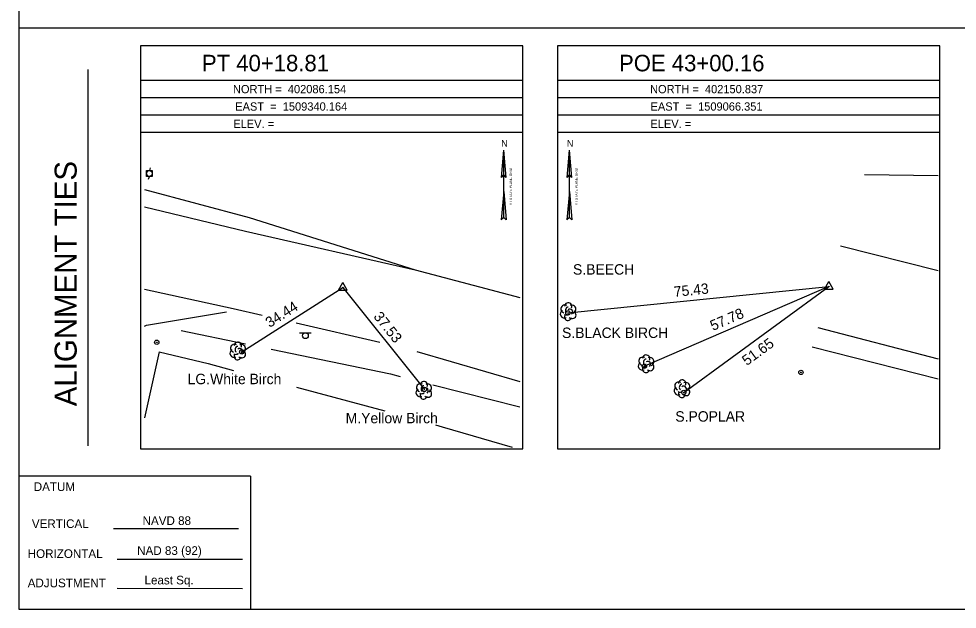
# Model space of a CAD drawing. Extents: x 1508412 to 1509054, y 401108 to 401963.
# Drawn here: x 1508411.9 to 1508681.9, y 401107.7 to 401277.6 of the extents above; entities that cross this region are included whole.
import ezdxf

# ---------------------------------------------------------------- set-up
doc = ezdxf.new("R2010")
doc.units = 0
for name, color, linetype in [('CBP', 7, 'Continuous'), ('CPH', 7, 'Continuous'), ('Default', 7, 'Continuous'), ('L_C', 7, 'Continuous'), ('LAWA', 7, 'Continuous'), ('LFP', 7, 'Continuous'), ('LTD', 7, 'Continuous'), ('LWS', 7, 'Continuous'), ('MPIP', 7, 'Continuous'), ('NBL1', 7, 'Continuous'), ('NBL2', 7, 'Continuous'), ('NNA_P', 7, 'Continuous'), ('PET', 7, 'Continuous'), ('PSU', 7, 'Continuous'), ('RDP', 7, 'Continuous'), ('SSGN', 7, 'Continuous'), ('UP', 7, 'Continuous')]:
    doc.layers.add(name, color=color, linetype=linetype)

msp = doc.modelspace()

# ---------------------------------------------------------------- linework, layer by layer
at = {"layer": 'CBP'}
for centre, radius in [((1508569.92, 401192.97), 0.625), ((1508569.92, 401192.97), 0.0833), ((1508476.08, 401181.78), 0.625), ((1508476.08, 401181.78), 0.0833), ((1508591.91, 401177.64), 0.625), ((1508591.91, 401177.64), 0.0833), ((1508528.62, 401170.99), 0.625), ((1508528.62, 401170.99), 0.0833), ((1508603.23, 401170.12), 0.625), ((1508603.23, 401170.12), 0.0833)]:
    msp.add_circle(centre, radius, dxfattribs=at)
at = {"layer": 'CPH'}
for p, q in [((1508503.89, 401199.55), (1508505.14, 401201.72)), ((1508506.39, 401199.55), (1508505.14, 401201.72)), ((1508643.72, 401199.83), (1508644.97, 401202)), ((1508646.22, 401199.83), (1508644.97, 401202)), ((1508644.97, 401200.55), (1508644.97, 401200.55)), ((1508503.89, 401199.55), (1508506.39, 401199.55)), ((1508505.14, 401200.27), (1508505.14, 401200.27)), ((1508643.72, 401199.83), (1508646.22, 401199.83))]:
    msp.add_line(p, q, dxfattribs=at)
for centre in [(1508644.97, 401200.55), (1508505.14, 401200.27)]:
    msp.add_circle(centre, 0.0833, dxfattribs=at)
at = {"layer": 'Default'}
for p, q in [((1508569.92, 401192.97), (1508644.97, 401200.55)), ((1508644.97, 401200.55), (1508591.91, 401177.64)), ((1508603.23, 401170.12), (1508644.97, 401200.55)), ((1508476.08, 401181.78), (1508505.14, 401200.27)), ((1508505.14, 401200.27), (1508528.62, 401170.99))]:
    msp.add_line(p, q, dxfattribs=at)
at = {"layer": 'LAWA'}
for points in [[(1508655.19, 401232.86), (1508676.45, 401232.52)], [(1508458.66, 401187.96), (1508477.14, 401184.1)], [(1508484.53, 401182.56), (1508518.81, 401175.41), (1508521.6, 401174.71)], [(1508531.02, 401172.33), (1508556.1, 401166)]]:
    msp.add_lwpolyline(points, dxfattribs=at)
at = {"layer": 'LFP'}
for radius in [0.625, 0.0833]:
    msp.add_circle((1508636.94, 401175.87), radius, dxfattribs=at)
at = {"layer": 'LTD'}
for p, q in [((1508569.95, 401193.41), (1508569.95, 401193.41)), ((1508569.95, 401193.41), (1508569.95, 401193.41)), ((1508474.9, 401182.09), (1508474.9, 401182.09)), ((1508474.9, 401182.09), (1508474.9, 401182.09)), ((1508592.38, 401178.4), (1508592.38, 401178.4)), ((1508592.38, 401178.4), (1508592.38, 401178.4)), ((1508602.7, 401171.23), (1508602.7, 401171.23)), ((1508602.7, 401171.23), (1508602.7, 401171.23)), ((1508528.42, 401170.77), (1508528.42, 401170.77)), ((1508528.42, 401170.77), (1508528.42, 401170.77))]:
    msp.add_line(p, q, dxfattribs=at)
for centre in [(1508569.99, 401194.85), (1508474.94, 401183.53), (1508592.43, 401179.84), (1508602.75, 401172.66), (1508528.46, 401172.2)]:
    msp.add_arc(centre, 1.05, 335.5272, 180.9563, dxfattribs=at)
for centre, major_axis, ratio, start_param, end_param in [((1508569.16, 401194.08), (1.21, -0.51), 0.895232, 1.570796, 4.712389), ((1508570.99, 401194), (-1.14, -0.48), 0.949671, 1.570796, 4.712389), ((1508568.86, 401192.7), (0.58, -1.04), 0.959034, 3.141593, 6.283185), ((1508569.49, 401192.66), (-0.625, -0.083), 0.423636, 0, 3.141593), ((1508569.74, 401193.87), (-0.208, -0.792), 0.645439, 3.141593, 6.283185), ((1508570.45, 401193.25), (-0.5, 0.667), 0.989748, 3.141593, 6.283185), ((1508570.95, 401192.58), (-1.09, 0.79), 0.841452, 1.570796, 4.712389), ((1508569.95, 401191.91), (0.26, 1.06), 0.942809, 1.570796, 4.712389), ((1508473.81, 401181.38), (0.58, -1.04), 0.959034, 3.141593, 6.283185), ((1508474.11, 401182.76), (1.21, -0.51), 0.895232, 1.570796, 4.712389), ((1508474.69, 401182.55), (-0.208, -0.792), 0.645439, 3.141593, 6.283185), ((1508475.4, 401181.93), (-0.5, 0.667), 0.989748, 3.141593, 6.283185), ((1508475.9, 401181.26), (-1.09, 0.79), 0.841452, 1.570796, 4.712389), ((1508475.94, 401182.68), (-1.14, -0.48), 0.949671, 1.570796, 4.712389), ((1508474.9, 401180.59), (0.26, 1.06), 0.942809, 1.570796, 4.712389), ((1508474.44, 401181.34), (-0.625, -0.083), 0.423636, 0, 3.141593), ((1508591.59, 401179.07), (1.21, -0.51), 0.895232, 1.570796, 4.712389), ((1508592.17, 401178.86), (-0.208, -0.792), 0.645439, 3.141593, 6.283185), ((1508592.88, 401178.23), (-0.5, 0.667), 0.989748, 3.141593, 6.283185), ((1508593.42, 401178.98), (-1.14, -0.48), 0.949671, 1.570796, 4.712389), ((1508591.3, 401177.69), (0.58, -1.04), 0.959034, 3.141593, 6.283185), ((1508592.38, 401176.9), (0.26, 1.06), 0.942809, 1.570796, 4.712389), ((1508591.92, 401177.65), (-0.625, -0.083), 0.423636, 0, 3.141593), ((1508593.38, 401177.57), (-1.09, 0.79), 0.841452, 1.570796, 4.712389), ((1508527.33, 401170.06), (0.58, -1.04), 0.959034, 3.141593, 6.283185), ((1508527.62, 401171.43), (1.21, -0.51), 0.895232, 1.570796, 4.712389), ((1508528.21, 401171.23), (-0.208, -0.792), 0.645439, 3.141593, 6.283185), ((1508528.92, 401170.6), (-0.5, 0.667), 0.989748, 3.141593, 6.283185), ((1508529.42, 401169.93), (-1.09, 0.79), 0.841452, 1.570796, 4.712389), ((1508529.46, 401171.35), (-1.14, -0.48), 0.949671, 1.570796, 4.712389), ((1508601.62, 401170.52), (0.58, -1.04), 0.959034, 3.141593, 6.283185), ((1508601.91, 401171.9), (1.21, -0.51), 0.895232, 1.570796, 4.712389), ((1508602.5, 401171.69), (-0.208, -0.792), 0.645439, 3.141593, 6.283185), ((1508603.2, 401171.06), (-0.5, 0.667), 0.989748, 3.141593, 6.283185), ((1508603.7, 401170.4), (-1.09, 0.79), 0.841452, 1.570796, 4.712389), ((1508603.75, 401171.81), (-1.14, -0.48), 0.949671, 1.570796, 4.712389), ((1508528.42, 401169.27), (0.26, 1.06), 0.942809, 1.570796, 4.712389), ((1508527.96, 401170.02), (-0.625, -0.083), 0.423636, 0, 3.141593), ((1508602.7, 401169.73), (0.26, 1.06), 0.942809, 1.570796, 4.712389), ((1508602.25, 401170.48), (-0.625, -0.083), 0.423636, 0, 3.141593)]:
    msp.add_ellipse(centre, major_axis=major_axis, ratio=ratio, start_param=start_param, end_param=end_param, dxfattribs=at)
at = {"layer": 'LWS'}
for points in [[(1508452.28, 401181.82), (1508448.04, 401162.82)], [(1508452.28, 401181.82), (1508466.44, 401178.39)], [(1508640.16, 401183.27), (1508676.45, 401174.06)], [(1508466.44, 401178.39), (1508473.7, 401176.45)], [(1508491.85, 401171.59), (1508517.26, 401164.79)], [(1508533.86, 401160.09), (1508531.92, 401160.64)], [(1508553.92, 401154.24), (1508533.86, 401160.09)]]:
    msp.add_lwpolyline(points, dxfattribs=at)
at = {"layer": 'MPIP'}
for radius in [0.625, 0.0833]:
    msp.add_circle((1508451.62, 401184.53), radius, dxfattribs=at)
at = {"layer": 'NBL1'}
msp.add_lwpolyline([(1508411.91, 401107.72), (1509051.91, 401107.72), (1509051.91, 401527.72), (1508411.91, 401527.72)], close=True, dxfattribs=at)
at = {"layer": 'NBL2'}
for p, q in [((1508411.91, 401275.05), (1509051.91, 401275.05)), ((1508431.91, 401154.72), (1508431.91, 401263.05)), ((1508556.91, 401259.88), (1508446.91, 401259.88)), ((1508676.91, 401259.88), (1508566.91, 401259.88)), ((1508556.91, 401254.88), (1508446.91, 401254.88)), ((1508676.91, 401254.88), (1508566.91, 401254.88)), ((1508556.91, 401249.88), (1508446.91, 401249.88)), ((1508676.91, 401249.88), (1508566.91, 401249.88)), ((1508556.91, 401244.88), (1508446.91, 401244.88)), ((1508676.91, 401244.88), (1508566.91, 401244.88)), ((1508478.57, 401145.97), (1508411.91, 401145.97)), ((1508478.57, 401145.97), (1508478.57, 401107.72)), ((1508478.57, 401145.97), (1508478.57, 401107.72)), ((1508439.15, 401130.95), (1508475.15, 401130.91)), ((1508440.26, 401122.17), (1508476.26, 401122.17)), ((1508440.26, 401113.74), (1508476.26, 401113.7))]:
    msp.add_line(p, q, dxfattribs=at)
for points in [[(1508446.91, 401153.88), (1508556.91, 401153.88), (1508556.91, 401269.88), (1508446.91, 401269.88)], [(1508566.91, 401153.88), (1508676.91, 401153.88), (1508676.91, 401269.88), (1508566.91, 401269.88)]]:
    msp.add_lwpolyline(points, close=True, dxfattribs=at)
at = {"layer": 'NNA_P'}
for p, q in [((1508550.75, 401231.99), (1508551.45, 401239.78)), ((1508551.45, 401220.4), (1508551.45, 401239.78)), ((1508552.14, 401231.99), (1508551.45, 401239.78)), ((1508569.65, 401231.99), (1508570.34, 401239.78)), ((1508570.35, 401220.4), (1508570.34, 401239.78)), ((1508571.04, 401231.99), (1508570.34, 401239.78)), ((1508550.75, 401231.99), (1508551.45, 401232.75)), ((1508552.14, 401231.99), (1508551.45, 401232.75)), ((1508569.65, 401231.99), (1508570.35, 401232.75)), ((1508571.04, 401231.99), (1508570.35, 401232.75)), ((1508551.45, 401227.93), (1508550.73, 401219.77)), ((1508551.45, 401227.93), (1508552.17, 401219.77)), ((1508570.35, 401227.93), (1508569.63, 401219.77)), ((1508570.35, 401227.93), (1508571.07, 401219.77)), ((1508551.45, 401220.4), (1508550.73, 401219.77)), ((1508551.45, 401220.4), (1508552.17, 401219.77)), ((1508570.35, 401220.4), (1508569.63, 401219.77)), ((1508570.35, 401220.4), (1508571.07, 401219.77))]:
    msp.add_line(p, q, dxfattribs=at)
at = {"layer": 'PET'}
for points in [[(1508448.04, 401223.49), (1508477.12, 401216.53), (1508525.99, 401205.41), (1508556.1, 401197.39)], [(1508648.35, 401212.32), (1508676.45, 401205.17)], [(1508448.04, 401199.84), (1508473.63, 401194.26), (1508481.9, 401192.37)], [(1508491.72, 401190.11), (1508515.78, 401184.6)], [(1508641.78, 401188.81), (1508676.45, 401179.78)], [(1508526.39, 401181.84), (1508556.1, 401173.27)]]:
    msp.add_lwpolyline(points, dxfattribs=at)
at = {"layer": 'PSU'}
msp.add_lwpolyline([(1508448.04, 401228.53), (1508478.16, 401220.4), (1508525.99, 401205.41)], dxfattribs=at)
at = {"layer": 'RDP'}
msp.add_lwpolyline([(1508448.04, 401189.13), (1508448.7, 401189.45), (1508471.72, 401193.34)], dxfattribs=at)
at = {"layer": 'SSGN'}
for p, q in [((1508492.72, 401187.27), (1508496.05, 401187.27)), ((1508494.37, 401186.44), (1508494.37, 401186.44))]:
    msp.add_line(p, q, dxfattribs=at)
msp.add_circle((1508494.37, 401186.44), 0.833, dxfattribs=at)
at = {"layer": 'UP'}
for p, q in [((1508448.66, 401232.26), (1508448.66, 401233.93)), ((1508448.66, 401233.93), (1508450.33, 401233.93)), ((1508449.74, 401234.76), (1508449.49, 401233.93)), ((1508449.49, 401233.1), (1508449.49, 401233.1)), ((1508450.33, 401233.93), (1508450.33, 401232.26)), ((1508450.33, 401232.26), (1508448.66, 401232.26)), ((1508449.24, 401231.43), (1508449.49, 401232.26))]:
    msp.add_line(p, q, dxfattribs=at)
msp.add_circle((1508449.49, 401233.1), 0.833, dxfattribs=at)

# ---------------------------------------------------------------- texts
at = {"layer": 'Default'}
for s, rotation, p in [('75.43', 5.7724, (1508600.53, 401197.57)), ('34.44', 32.4766, (1508484.08, 401188.64)), ('37.53', 308.7243, (1508513.8, 401191.87)), ('57.78', 23.3581, (1508611.61, 401187.78)), ('51.65', 36.0964, (1508621.38, 401177.68))]:
    msp.add_text(s, height=3, rotation=rotation, dxfattribs=at).set_placement(p)
at = {"layer": 'L_C'}
for s, p in [('S.BEECH', (1508571.36, 401204.01)), ('S.BLACK BIRCH', (1508568.21, 401185.77)), ('LG.White Birch', (1508460.48, 401172.48)), ('M.Yellow Birch', (1508505.96, 401161.23)), ('S.POPLAR', (1508600.8, 401161.7))]:
    msp.add_text(s, height=3, dxfattribs=at).set_placement(p)
at = {"layer": 'NBL2'}
for s, height, p in [('    PT 40+18.81    ', 4.75, (1508457.55, 401262.51)), ('    POE 43+00.16   ', 4.75, (1508577.55, 401262.51)), ('NORTH =  402086.154 ', 2.375, (1508473.53, 401256.2)), ('NORTH =  402150.837 ', 2.375, (1508593.53, 401256.2)), ('EAST  =  1509340.164', 2.375, (1508474.18, 401251.2)), ('EAST  =  1509066.351', 2.375, (1508593.67, 401251.2)), ('ELEV. =             ', 2.375, (1508473.63, 401246.2)), ('ELEV. =             ', 2.375, (1508593.63, 401246.2)), ('DATUM', 2.5, (1508416.22, 401141.73)), ('  NAVD 88 ', 2.5, (1508445.67, 401131.96)), ('HORIZONTAL', 2.5, (1508414.48, 401122.47)), ('NAD 83 (92)', 2.5, (1508445.97, 401123.34)), (' Least Sq.', 2.5, (1508447.16, 401114.86)), ('ADJUSTMENT', 2.5, (1508414.48, 401114.03))]:
    msp.add_text(s, height=height, dxfattribs=at).set_placement(p)
for s, height, rotation, p in [('ALIGNMENT TIES', 6.3332, 90, (1508428.57, 401166.12)), ('VERTICAL', 2.5, 0.1439, (1508415.68, 401131.06))]:
    msp.add_text(s, height=height, rotation=rotation, dxfattribs=at).set_placement(p)
at = {"layer": 'NNA_P'}
for p in [(1508550.69, 401240.79), (1508569.58, 401240.79)]:
    msp.add_text('N', height=1.97, dxfattribs=at).set_placement(p)
for p in [(1508553.8, 401223.97), (1508572.7, 401223.97)]:
    msp.add_text('VT STATE PLANE GRID', height=0.7, rotation=90.0204, dxfattribs=at).set_placement(p)

doc.saveas('drawing.dxf')
